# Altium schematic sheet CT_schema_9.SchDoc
size 147 x 119 mm
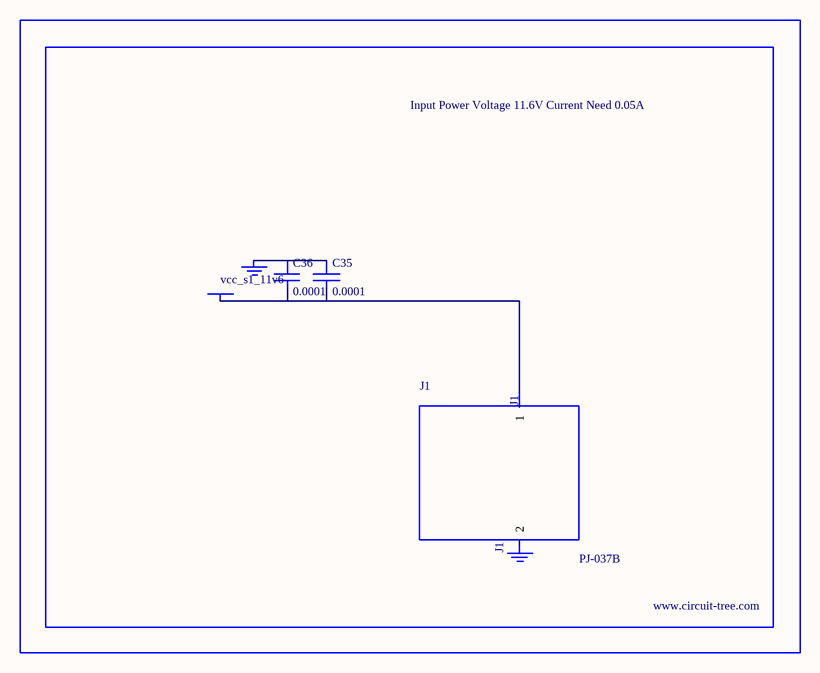
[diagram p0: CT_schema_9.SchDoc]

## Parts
BORDER8  (no value)
C35  0.0001  [EXV-9H]
C36  0.0001  [EXV-9H]
GND_INSTANCE_8_0  (no value)
GND_INSTANCE_8_1  (no value)
J1  PJ-037B  [PJ-037B_PACKAGE]
POWER_INSTANCE_8_0  vcc_s1_11v6

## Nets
NetC35_1: C35.1 C36.1 GND_INSTANCE_8_0.0(GND)
NetC35_2: C35.2 C36.2 J1.1 POWER_INSTANCE_8_0.0(PWR)

Not connected (* = marked no-connect by the designer): GND_INSTANCE_8_1 0(GND); J1 2

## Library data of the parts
BORDER8 = BORDER_PAGE8
C35 C36 = EDK107M035A9HAA
GND_INSTANCE_8_0 GND_INSTANCE_8_1 = GND
POWER_INSTANCE_8_0 = PWR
